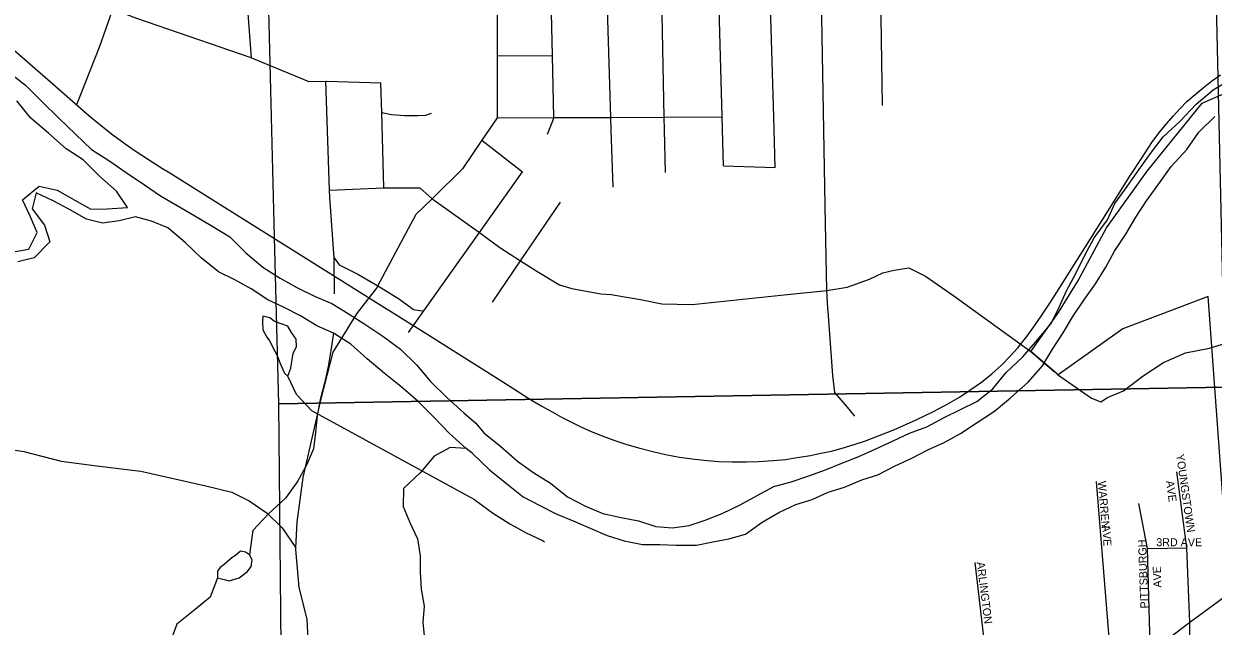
# Model space of a CAD drawing. Extents: x -37878.7 to -37844.7, y -19791.4 to -19769.4.
# Drawn here: x -37872.428 to -37871.021, y -19776.611 to -19775.898 of the extents above; entities that cross this region are included whole.
import ezdxf

# ---------------------------------------------------------------- set-up
doc = ezdxf.new("R2010")
doc.units = 0
for name, color, linetype in [('GM_X_City_Street', 7, 'Continuous'), ('GM_X_Corporation', 7, 'Continuous'), ('GM_X_County_Road', 7, 'Continuous'), ('GM_X_Major_River', 7, 'Continuous'), ('GM_X_Minor_Lake', 7, 'Continuous'), ('GM_X_Minor_River', 7, 'Continuous'), ('GM_X_Rail_Line', 7, 'Continuous'), ('GM_X_Section', 7, 'Continuous'), ('GM_X_Township_Road', 7, 'Continuous'), ('GM_X_Township_Subdivision', 7, 'Continuous'), ('GM_X_Township_Subdivision_Text', 7, 'Continuous')]:
    doc.layers.add(name, color=color, linetype=linetype)

msp = doc.modelspace()

# ---------------------------------------------------------------- linework, layer by layer
at = {"layer": 'GM_X_City_Street'}
for points in [[(-37871.8635, -19775.4515), (-37871.8595, -19775.5592), (-37871.868, -19775.6505), (-37871.868, -19775.7236), (-37871.868, -19775.795), (-37871.868, -19775.8689), (-37871.868, -19775.9359), (-37871.868, -19776.0094), (-37871.8859, -19776.0358), (-37871.9087, -19776.0695), (-37871.9432, -19776.1035)], [(-37871.4122, -19775.9946), (-37871.4138, -19775.8907), (-37871.4176, -19775.6493), (-37871.4065, -19775.4521)], [(-37871.733, -19776.0239), (-37871.733, -19776.0239), (-37871.7334, -19776.0088), (-37871.7379, -19775.8671), (-37871.7425, -19775.7217), (-37871.7448, -19775.6487)], [(-37871.6699, -19776.0234), (-37871.6702, -19776.0085), (-37871.6732, -19775.8662), (-37871.6763, -19775.7207), (-37871.6778, -19775.6482)], [(-37871.6001, -19776.0663), (-37871.6018, -19776.0082), (-37871.6058, -19775.8653), (-37871.6099, -19775.7197), (-37871.6119, -19775.6485)], [(-37871.5408, -19776.008), (-37871.5408, -19776.008), (-37871.545, -19775.8645), (-37871.5492, -19775.7188), (-37871.5512, -19775.6487)], [(-37871.4799, -19776.1129), (-37871.484, -19775.8903), (-37871.4845, -19775.8637), (-37871.4872, -19775.7179), (-37871.4885, -19775.649), (-37871.4885, -19775.6473), (-37871.4871, -19775.6392)], [(-37871.8007, -19776.0091), (-37871.8025, -19775.9354), (-37871.8042, -19775.868), (-37871.8061, -19775.793), (-37871.8078, -19775.7227), (-37871.8096, -19775.6497)], [(-37872.1584, -19775.9385), (-37872.1627, -19775.8806), (-37872.1667, -19775.7862), (-37872.1668, -19775.7532), (-37872.1624, -19775.7393), (-37872.1567, -19775.7279)], [(-37872.3651, -19775.9935), (-37872.3378, -19775.9245), (-37872.3236, -19775.8843)], [(-37872.3272, -19775.879), (-37872.3269, -19775.8791), (-37872.3224, -19775.8808), (-37872.2943, -19775.8913), (-37872.1594, -19775.9381), (-37872.1584, -19775.9385), (-37872.0905, -19775.9662), (-37872.0704, -19775.9658), (-37872.0696, -19775.9658), (-37872.0054, -19775.9679)], [(-37871.868, -19775.9359), (-37871.8025, -19775.9354)], [(-37872.0601, -19776.2175), (-37872.0605, -19776.175), (-37872.066, -19776.1035), (-37872.0663, -19776.095), (-37872.0704, -19775.9658)], [(-37872.0018, -19776.092), (-37872.0044, -19776.0032), (-37872.0054, -19775.9679)], [(-37872.0044, -19776.0032), (-37871.9928, -19776.0052), (-37871.9776, -19776.0066), (-37871.9617, -19776.0066), (-37871.9521, -19776.006), (-37871.9457, -19776.004)], [(-37871.868, -19776.0094), (-37871.8007, -19776.0091), (-37871.7334, -19776.0088), (-37871.6702, -19776.0085), (-37871.6018, -19776.0082)], [(-37871.8085, -19776.0287), (-37871.8014, -19776.0108), (-37871.8007, -19776.0091)], [(-37871.5391, -19776.0679), (-37871.5408, -19776.008)], [(-37871.7308, -19776.0912), (-37871.733, -19776.0239)], [(-37871.6688, -19776.0741), (-37871.6699, -19776.0234), (-37871.6699, -19776.0234)], [(-37871.8859, -19776.0358), (-37871.8378, -19776.0732)], [(-37871.6001, -19776.0663), (-37871.5391, -19776.0679)], [(-37871.9727, -19776.2632), (-37871.9545, -19776.2375), (-37871.8889, -19776.1452), (-37871.8378, -19776.0732)], [(-37872.0663, -19776.095), (-37872.0018, -19776.092), (-37871.9982, -19776.092)], [(-37871.9982, -19776.092), (-37871.9594, -19776.092), (-37871.9448, -19776.105)], [(-37872.0248, -19776.2296), (-37872.0247, -19776.2295), (-37872.0102, -19776.2107), (-37872.0089, -19776.2082), (-37871.9638, -19776.1233), (-37871.9448, -19776.105)], [(-37871.9432, -19776.1035), (-37871.9448, -19776.105), (-37871.9423, -19776.1067), (-37871.8889, -19776.1452), (-37871.8646, -19776.1627), (-37871.8401, -19776.1785), (-37871.821, -19776.1909), (-37871.794, -19776.2069), (-37871.7794, -19776.2111), (-37871.7451, -19776.2175), (-37871.7329, -19776.2183), (-37871.7173, -19776.221), (-37871.6982, -19776.2243), (-37871.673, -19776.2293), (-37871.6373, -19776.23), (-37871.5323, -19776.2193), (-37871.4781, -19776.2137)], [(-37871.8734, -19776.2275), (-37871.8401, -19776.1785), (-37871.7928, -19776.1091)], [(-37871.4781, -19776.2137), (-37871.4799, -19776.1143), (-37871.4799, -19776.1129)], [(-37872.0605, -19776.175), (-37872.0549, -19776.1832), (-37872.0325, -19776.1945), (-37872.0089, -19776.2082), (-37872.005, -19776.2105), (-37871.9836, -19776.2237), (-37871.9668, -19776.236), (-37871.9592, -19776.2372), (-37871.9545, -19776.2375)], [(-37871.4781, -19776.2137), (-37871.4781, -19776.2137), (-37871.4539, -19776.2097), (-37871.4275, -19776.2002), (-37871.4118, -19776.1926), (-37871.3982, -19776.1896), (-37871.3811, -19776.1869), (-37871.3611, -19776.1967), (-37871.3279, -19776.2198), (-37871.2366, -19776.2859), (-37871.2281, -19776.2932)], [(-37871.4766, -19776.2347), (-37871.4781, -19776.2137)], [(-37872.0924, -19776.6105), (-37872.0928, -19776.6027), (-37872.1021, -19776.565), (-37872.1062, -19776.5199), (-37872.1061, -19776.518), (-37872.1043, -19776.4879), (-37872.0973, -19776.435), (-37872.076, -19776.3418), (-37872.0618, -19776.2867), (-37872.0337, -19776.2412), (-37872.0248, -19776.2296)], [(-37871.445, -19776.3624), (-37871.4537, -19776.3517), (-37871.4686, -19776.3343), (-37871.4707, -19776.3142), (-37871.4763, -19776.2381), (-37871.4766, -19776.2347)], [(-37871.0255, -19776.2817), (-37870.9754, -19776.2663), (-37870.9113, -19776.2624), (-37870.8612, -19776.2596), (-37870.8162, -19776.2657), (-37870.7909, -19776.2757), (-37870.7508, -19776.2998), (-37870.6481, -19776.3552)], [(-37872.4479, -19776.401), (-37872.4277, -19776.4043), (-37872.3836, -19776.4156), (-37872.3413, -19776.4212), (-37872.2895, -19776.4275), (-37872.2126, -19776.4447), (-37872.1816, -19776.4523), (-37872.1611, -19776.4625), (-37872.1401, -19776.4772), (-37872.122, -19776.4944), (-37872.1061, -19776.518)]]:
    msp.add_lwpolyline(points, dxfattribs=at)
at = {"layer": 'GM_X_Corporation'}
msp.add_lwpolyline([(-37871.0014, -19776.5712), (-37871.027, -19776.2209), (-37871.0728, -19776.2381), (-37871.1277, -19776.259), (-37871.2043, -19776.3136), (-37871.2366, -19776.2859), (-37871.2041, -19776.2398), (-37871.1811, -19776.2026), (-37871.1471, -19776.1394), (-37871.0991, -19776.0723), (-37871.034, -19775.9918), (-37870.992, -19775.9735)], dxfattribs=at)
at = {"layer": 'GM_X_County_Road'}
for points in [[(-37871.2281, -19776.2932), (-37871.2281, -19776.2932), (-37871.2096, -19776.3091), (-37871.2051, -19776.3129), (-37871.165, -19776.3412), (-37871.1538, -19776.3454), (-37871.146, -19776.3403), (-37871.1272, -19776.3322), (-37871.1037, -19776.3145), (-37871.0798, -19776.299), (-37871.0538, -19776.2873), (-37871.0255, -19776.2817)], [(-37871.0832, -19776.6324), (-37871.0487, -19776.6062), (-37871.0014, -19776.5712)]]:
    msp.add_lwpolyline(points, dxfattribs=at)
at = {"layer": 'GM_X_Major_River'}
for points in [[(-37872.5285, -19775.886), (-37872.5093, -19775.9001), (-37872.4869, -19775.9208), (-37872.4673, -19775.9352), (-37872.4476, -19775.9538), (-37872.4256, -19775.9708), (-37872.4062, -19775.9905), (-37872.3865, -19776.0098), (-37872.3668, -19776.0287), (-37872.3475, -19776.0469), (-37872.3271, -19776.0597), (-37872.3068, -19776.0741), (-37872.2852, -19776.0888), (-37872.266, -19776.1017), (-37872.2465, -19776.113), (-37872.2254, -19776.1251), (-37872.2062, -19776.1369), (-37872.1839, -19776.15), (-37872.165, -19776.169), (-37872.1449, -19776.186), (-37872.1246, -19776.1989), (-37872.105, -19776.2102), (-37872.0832, -19776.2208)], [(-37871.8933, -19776.3708), (-37871.8835, -19776.3819), (-37871.8635, -19776.3984), (-37871.8439, -19776.4156), (-37871.8247, -19776.4293), (-37871.8047, -19776.4416), (-37871.7848, -19776.4576), (-37871.7633, -19776.4687), (-37871.7429, -19776.4776), (-37871.7213, -19776.4822), (-37871.7009, -19776.4861), (-37871.6801, -19776.4927), (-37871.6604, -19776.4943), (-37871.6407, -19776.4917), (-37871.6218, -19776.4853), (-37871.6016, -19776.4775), (-37871.5804, -19776.4673), (-37871.5595, -19776.4556), (-37871.5405, -19776.4455), (-37871.52, -19776.4399), (-37871.4991, -19776.4331), (-37871.4794, -19776.426), (-37871.4601, -19776.4181), (-37871.4403, -19776.4102), (-37871.421, -19776.4012), (-37871.3997, -19776.3915), (-37871.3803, -19776.3824), (-37871.3598, -19776.3749), (-37871.3393, -19776.364), (-37871.32, -19776.3546), (-37871.3006, -19776.3448), (-37871.2816, -19776.3301), (-37871.2659, -19776.3108), (-37871.2461, -19776.2923), (-37871.229, -19776.2719), (-37871.2125, -19776.2526), (-37871.2033, -19776.2333), (-37871.1945, -19776.2139), (-37871.1834, -19776.1935), (-37871.173, -19776.1719), (-37871.1616, -19776.1514), (-37871.1459, -19776.1302), (-37871.1375, -19776.1105), (-37871.1226, -19776.0905), (-37871.1088, -19776.0708), (-37871.0951, -19776.0515), (-37871.0802, -19776.0318), (-37871.0604, -19776.0137), (-37871.0413, -19775.9932), (-37871.0211, -19775.9762), (-37871.0014, -19775.9642)], [(-37872.4612, -19776.1715), (-37872.4219, -19776.1646), (-37872.4121, -19776.1451), (-37872.4201, -19776.1255), (-37872.4292, -19776.1063), (-37872.4095, -19776.09), (-37872.3882, -19776.0948), (-37872.3674, -19776.1069), (-37872.3483, -19776.1175), (-37872.329, -19776.1171), (-37872.3051, -19776.1154), (-37872.318, -19776.096), (-37872.3381, -19776.0782), (-37872.3575, -19776.0592), (-37872.3778, -19776.046), (-37872.3987, -19776.0275), (-37872.4195, -19776.0097), (-37872.4362, -19775.9892)], [(-37871.8973, -19776.4062), (-37871.8769, -19776.4257), (-37871.857, -19776.4421), (-37871.837, -19776.4577), (-37871.8174, -19776.4681), (-37871.7974, -19776.4781), (-37871.7781, -19776.4861), (-37871.7577, -19776.495), (-37871.7377, -19776.5034), (-37871.7177, -19776.51), (-37871.6958, -19776.5142), (-37871.6753, -19776.514), (-37871.656, -19776.5148), (-37871.6322, -19776.5149), (-37871.6128, -19776.5112), (-37871.5939, -19776.5075), (-37871.5742, -19776.5019), (-37871.5544, -19776.4876), (-37871.5346, -19776.4763), (-37871.5145, -19776.4669), (-37871.4955, -19776.4609), (-37871.4762, -19776.4522), (-37871.4572, -19776.4462), (-37871.4367, -19776.4376), (-37871.4177, -19776.4316), (-37871.3972, -19776.4211), (-37871.3775, -19776.4121), (-37871.3585, -19776.4023), (-37871.3391, -19776.3936), (-37871.3198, -19776.3827), (-37871.3, -19776.3699), (-37871.2798, -19776.3563), (-37871.2608, -19776.3408), (-37871.2399, -19776.3219), (-37871.2227, -19776.3027), (-37871.2112, -19776.283), (-37871.1986, -19776.2637), (-37871.1871, -19776.2443), (-37871.1741, -19776.225), (-37871.1604, -19776.2057), (-37871.1478, -19776.186), (-37871.1378, -19776.1671), (-37871.1244, -19776.147), (-37871.1126, -19776.127), (-37871.1, -19776.1077), (-37871.0851, -19776.0876), (-37871.0709, -19776.0668), (-37871.0523, -19776.0467), (-37871.0381, -19776.0263), (-37871.0191, -19776.0078)], [(-37871.8973, -19776.4062), (-37871.9044, -19776.4007), (-37871.9241, -19776.3829), (-37871.9423, -19776.3639), (-37871.9617, -19776.3446), (-37871.9817, -19776.3272), (-37872.0014, -19776.3116), (-37872.0218, -19776.2946), (-37872.0411, -19776.2772), (-37872.0615, -19776.264), (-37872.081, -19776.2553), (-37872.1005, -19776.2435), (-37872.1197, -19776.2337), (-37872.1392, -19776.2246), (-37872.1588, -19776.2118), (-37872.1783, -19776.2012), (-37872.1975, -19776.1917), (-37872.2179, -19776.1751), (-37872.2368, -19776.1569), (-37872.2573, -19776.1395), (-37872.2768, -19776.1315), (-37872.2958, -19776.1263), (-37872.315, -19776.1312), (-37872.3347, -19776.1339), (-37872.3537, -19776.1294), (-37872.3737, -19776.1177), (-37872.3932, -19776.1075), (-37872.4131, -19776.098), (-37872.418, -19776.1171), (-37872.4032, -19776.1365), (-37872.3971, -19776.1561), (-37872.4156, -19776.1751), (-37872.4349, -19776.1797)], [(-37872.0832, -19776.2208), (-37872.0633, -19776.2291), (-37872.0441, -19776.2408), (-37872.0234, -19776.2544), (-37872.003, -19776.2676), (-37871.9823, -19776.2831), (-37871.9633, -19776.3017), (-37871.9466, -19776.3215), (-37871.9273, -19776.3404), (-37871.9072, -19776.3582), (-37871.8933, -19776.3708)]]:
    msp.add_lwpolyline(points, dxfattribs=at)
at = {"layer": 'GM_X_Minor_Lake'}
for p, q in [((-37872.137, -19776.2732), (-37872.1307, -19776.2856)), ((-37872.1813, -19776.5296), (-37872.1906, -19776.5377))]:
    msp.add_line(p, q, dxfattribs=at)
for points in [[(-37872.1307, -19776.2856), (-37872.128, -19776.2904), (-37872.1244, -19776.3002), (-37872.1212, -19776.307), (-37872.1196, -19776.3115), (-37872.1153, -19776.3148), (-37872.1121, -19776.3057), (-37872.1091, -19776.2877), (-37872.1051, -19776.2804), (-37872.1056, -19776.2714), (-37872.1111, -19776.2635), (-37872.1154, -19776.256), (-37872.1246, -19776.2528), (-37872.1315, -19776.2499), (-37872.1369, -19776.2458), (-37872.1452, -19776.2441), (-37872.1455, -19776.2498), (-37872.1449, -19776.26), (-37872.1402, -19776.2687), (-37872.137, -19776.2732)], [(-37872.1906, -19776.5377), (-37872.1955, -19776.5412), (-37872.1988, -19776.5459), (-37872.1986, -19776.5535), (-37872.1906, -19776.5556), (-37872.1849, -19776.557), (-37872.1729, -19776.5537), (-37872.1632, -19776.5463), (-37872.1587, -19776.5401), (-37872.1578, -19776.5325), (-37872.1609, -19776.5265), (-37872.1655, -19776.5231), (-37872.1716, -19776.5221), (-37872.1772, -19776.5272), (-37872.1813, -19776.5296)]]:
    msp.add_lwpolyline(points, dxfattribs=at)
at = {"layer": 'GM_X_Minor_River'}
for points in [[(-37872.0615, -19776.264), (-37872.0648, -19776.2845), (-37872.0678, -19776.3036), (-37872.0723, -19776.3234), (-37872.0772, -19776.3429), (-37872.0806, -19776.3619), (-37872.0829, -19776.3817), (-37872.0851, -19776.4011), (-37872.0934, -19776.4203), (-37872.104, -19776.4395), (-37872.1184, -19776.4595), (-37872.1384, -19776.4778), (-37872.157, -19776.4975), (-37872.1596, -19776.5173), (-37872.1609, -19776.5265)], [(-37871.8942, -19776.4613), (-37872.0872, -19776.356), (-37872.1054, -19776.3366), (-37872.1153, -19776.3148)], [(-37871.9044, -19776.4007), (-37871.9234, -19776.3992), (-37871.9425, -19776.4098), (-37871.9584, -19776.4291), (-37871.9785, -19776.4478), (-37871.9791, -19776.4691), (-37871.9712, -19776.4883), (-37871.9621, -19776.5074), (-37871.959, -19776.5275), (-37871.959, -19776.5468), (-37871.9578, -19776.5669), (-37871.9543, -19776.587), (-37871.9558, -19776.6064), (-37871.9539, -19776.6257)], [(-37871.8942, -19776.4613), (-37871.8735, -19776.4766), (-37871.8531, -19776.4896), (-37871.8335, -19776.5003), (-37871.8142, -19776.5095), (-37871.812, -19776.511)], [(-37872.1986, -19776.5535), (-37872.2072, -19776.5764), (-37872.227, -19776.5928), (-37872.2467, -19776.6084), (-37872.2539, -19776.6279)]]:
    msp.add_lwpolyline(points, dxfattribs=at)
at = {"layer": 'GM_X_Rail_Line'}
for points in [[(-37872.4995, -19775.8773), (-37872.4508, -19775.9191), (-37872.3961, -19775.9668), (-37872.3508, -19776.0064), (-37872.336, -19776.0187), (-37872.3223, -19776.0296), (-37872.3079, -19776.0402), (-37872.296, -19776.0482), (-37872.2802, -19776.0586), (-37872.2637, -19776.0691), (-37872.2552, -19776.0744)], [(-37872.2552, -19776.0744), (-37872.1902, -19776.1151), (-37872.091, -19776.1773), (-37872.0105, -19776.228), (-37871.9529, -19776.2638), (-37871.8549, -19776.3256), (-37871.8303, -19776.3413), (-37871.8159, -19776.3499), (-37871.8028, -19776.3571), (-37871.7918, -19776.3634), (-37871.7807, -19776.3692), (-37871.7689, -19776.3748), (-37871.7567, -19776.3803), (-37871.7436, -19776.3857), (-37871.7298, -19776.3907), (-37871.7144, -19776.396), (-37871.6992, -19776.4003), (-37871.6836, -19776.4043), (-37871.6686, -19776.4076), (-37871.6521, -19776.4107), (-37871.634, -19776.4133), (-37871.6191, -19776.4149), (-37871.6056, -19776.4158), (-37871.5903, -19776.4165), (-37871.5733, -19776.4165), (-37871.5588, -19776.4161), (-37871.5415, -19776.4149), (-37871.5268, -19776.4134), (-37871.513, -19776.4113), (-37871.4971, -19776.4087), (-37871.4849, -19776.4062), (-37871.4724, -19776.4036), (-37871.4597, -19776.4001), (-37871.4457, -19776.3958), (-37871.4321, -19776.3914), (-37871.4181, -19776.3861), (-37871.3987, -19776.3784), (-37871.3725, -19776.3665), (-37871.3519, -19776.3568), (-37871.3348, -19776.3478), (-37871.321, -19776.3397), (-37871.3087, -19776.3316), (-37871.2949, -19776.3219), (-37871.2828, -19776.3121), (-37871.2714, -19776.3018), (-37871.2612, -19776.2914), (-37871.2521, -19776.2813), (-37871.2414, -19776.268), (-37871.2322, -19776.2553), (-37871.2244, -19776.244), (-37871.2135, -19776.2274), (-37871.2031, -19776.2111), (-37871.1727, -19776.1631), (-37871.1394, -19776.1099), (-37871.1202, -19776.0796), (-37871.1044, -19776.0549), (-37871.0934, -19776.0386), (-37871.0845, -19776.0264), (-37871.0764, -19776.0163), (-37871.0685, -19776.0072), (-37871.0606, -19775.9988), (-37871.052, -19775.9902), (-37871.0425, -19775.9817), (-37871.033, -19775.9737), (-37871.0229, -19775.9658), (-37871.0125, -19775.9586)]]:
    msp.add_lwpolyline(points, dxfattribs=at)
at = {"layer": 'GM_X_Section'}
msp.add_lwpolyline([(-37871.0324, -19775.2124), (-37871.0074, -19776.3279), (-37872.1261, -19776.3478), (-37872.1311, -19776.15), (-37872.1488, -19775.4398), (-37872.1545, -19775.2374), (-37871.0355, -19775.2124)], close=True, dxfattribs=at)
msp.add_lwpolyline([(-37872.1046, -19777.3854), (-37872.1081, -19777.2484), (-37872.123, -19776.676), (-37872.1261, -19776.3478), (-37871.0074, -19776.3279), (-37870.9803, -19777.3854)], dxfattribs=at)
at = {"layer": 'GM_X_Township_Road'}
msp.add_lwpolyline([(-37872.0751, -19777.3854), (-37872.0827, -19777.0084), (-37872.0885, -19776.6793), (-37872.0924, -19776.6107), (-37872.0924, -19776.6105)], dxfattribs=at)
at = {"layer": 'GM_X_Township_Subdivision'}
for points in [[(-37871.0494, -19776.5873), (-37871.052, -19776.5183), (-37871.064, -19776.428)], [(-37871.1425, -19776.6721), (-37871.1434, -19776.634), (-37871.1591, -19776.4395)], [(-37871.0954, -19776.6331), (-37871.0987, -19776.5188), (-37871.1091, -19776.4656)], [(-37871.0987, -19776.5188), (-37871.052, -19776.5183)], [(-37871.2865, -19776.7238), (-37871.2864, -19776.7212), (-37871.2906, -19776.6373), (-37871.3026, -19776.5353)], [(-37871.0484, -19776.6449), (-37871.0487, -19776.6062), (-37871.0494, -19776.5873)]]:
    msp.add_lwpolyline(points, dxfattribs=at)

# ---------------------------------------------------------------- texts
at = {"layer": 'GM_X_Township_Subdivision_Text'}
for s, rotation, p in [('YOUNGSTOWN', 278.049, (-37871.0649, -19776.4078)), ('WARREN', 274.845, (-37871.1574, -19776.4395)), ('AVE', 277.8561, (-37871.0769, -19776.4392)), ('AVE', 273.9506, (-37871.1524, -19776.4912)), ('3RD AVE', 0, (-37871.0883, -19776.5162)), ('PITTSBURGH', 92.0202, (-37871.0976, -19776.5897)), ('ARLINGTON', 277.1238, (-37871.3007, -19776.5353)), ('AVE', 91.9738, (-37871.0822, -19776.565))]:
    msp.add_text(s, height=0.00947, rotation=rotation, dxfattribs=at).set_placement(p)

doc.saveas('drawing.dxf')
